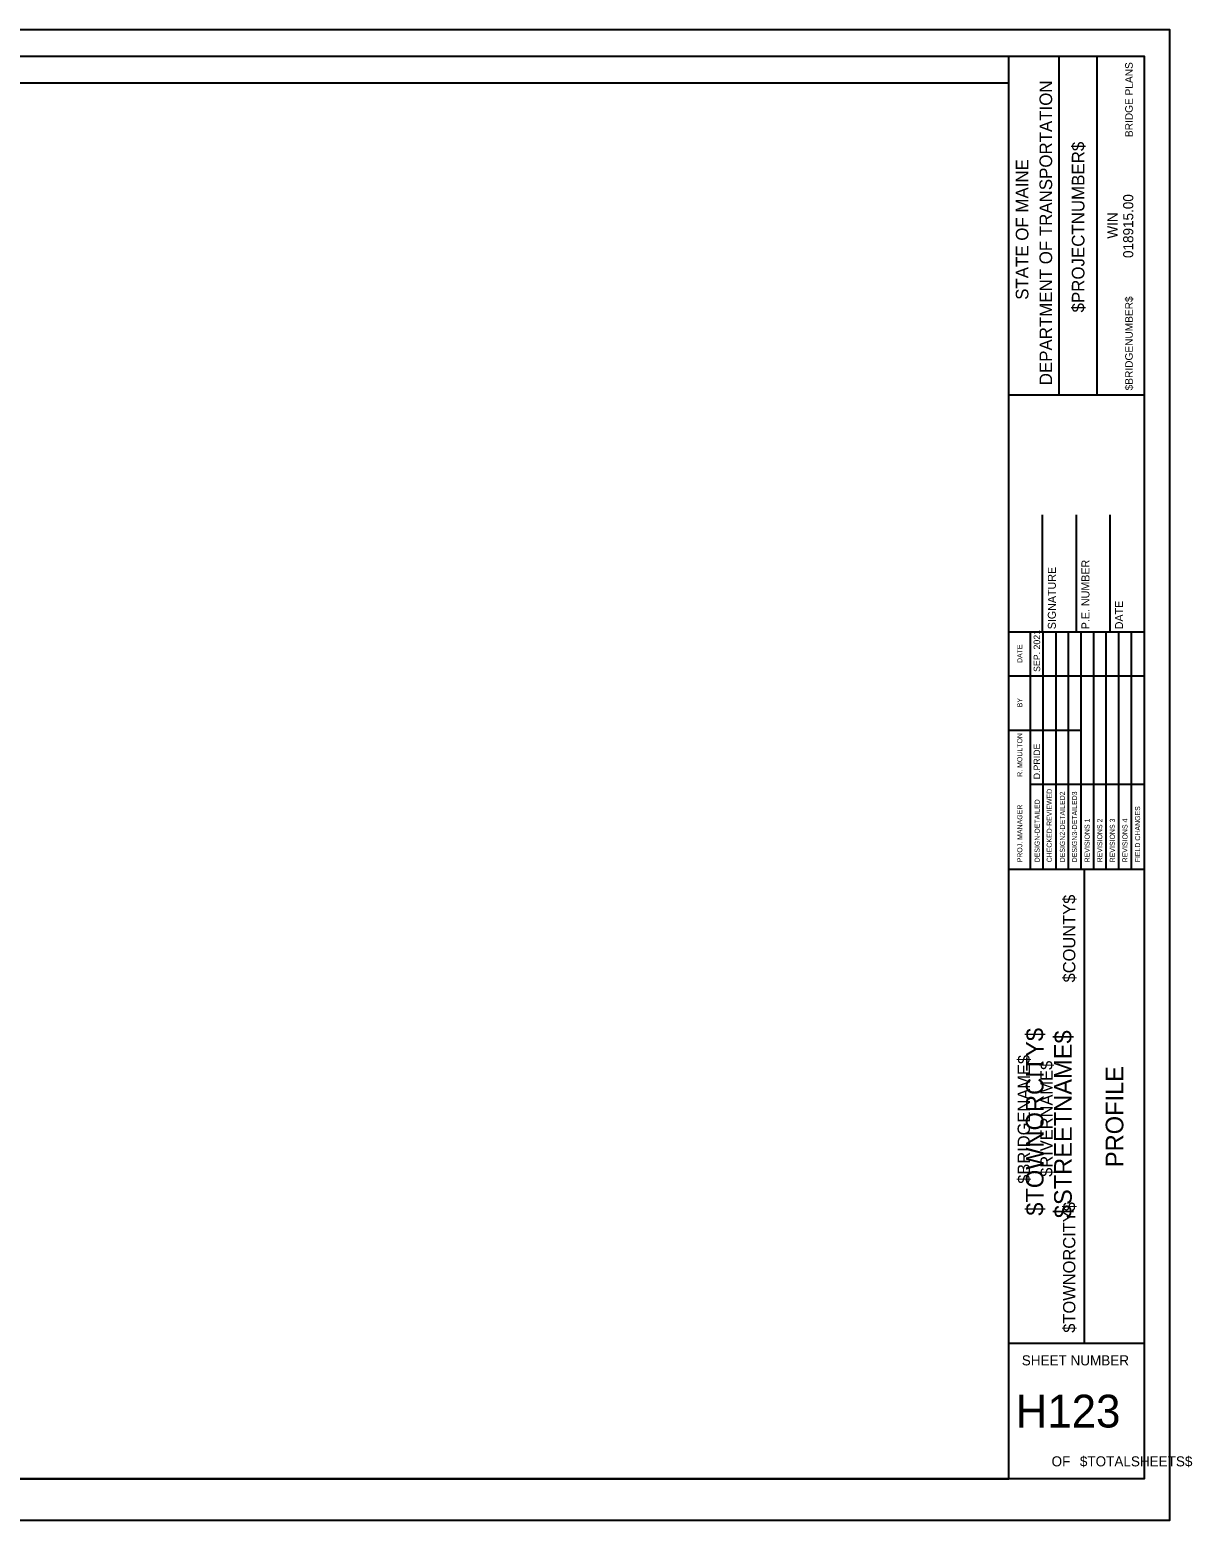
# Model space of a CAD drawing. Extents: x 53120 to 53979, y 9985 to 10535.
# Drawn here: x 53549 to 53979, y 9985 to 10535 of the extents above; entities that cross this region are included whole.
import ezdxf

# ---------------------------------------------------------------- set-up
doc = ezdxf.new("R2010")
doc.units = 0
for name, color, linetype in [('BORDER', 7, 'Continuous'), ('BRIDGE_TITLE', 7, 'Continuous'), ('CLIPS', 7, 'Continuous'), ('HIGHWAY_TITLE', 7, 'Continuous'), ('PLOT BOUNDARY', 7, 'Continuous')]:
    doc.layers.add(name, color=color, linetype=linetype)

msp = doc.modelspace()

# ---------------------------------------------------------------- linework, layer by layer
at = {"layer": 'BORDER'}
for p, q in [((53910.79, 10000), (53910.79, 10525)), ((53929.43, 10399.99), (53929.43, 10524.99)), ((53943.41, 10399.99), (53943.41, 10524.99)), ((53910.79, 10399.97), (53960.79, 10399.97)), ((53923.29, 10312.51), (53923.29, 10355.75)), ((53935.79, 10312.51), (53935.79, 10355.75)), ((53948.29, 10312.51), (53948.29, 10355.75)), ((53910.79, 10312.51), (53960.79, 10312.51)), ((53910.79, 10225.01), (53960.79, 10225.01)), ((53938.74, 10050.01), (53938.74, 10225.01)), ((53910.79, 10050.01), (53960.79, 10050.01))]:
    msp.add_line(p, q, dxfattribs=at)
msp.add_lwpolyline([(53160.79, 10525), (53960.79, 10525), (53960.79, 10000), (53160.79, 10000)], close=True, dxfattribs=at)
for points in [[(53918.86, 10296.26), (53918.86, 10312.51)], [(53923.53, 10225.03), (53923.53, 10312.51)], [(53928.18, 10312.51), (53928.18, 10225.03)], [(53932.84, 10225.03), (53932.84, 10312.51)], [(53937.5, 10225.03), (53937.5, 10312.51)], [(53942.16, 10225.03), (53942.16, 10312.51)], [(53946.82, 10225.03), (53946.82, 10312.51)], [(53951.48, 10225.03), (53951.48, 10312.51)], [(53956.13, 10225.03), (53956.13, 10312.51)], [(53918.87, 10225.03), (53918.87, 10308.98)], [(53910.79, 10296.26), (53960.79, 10296.26)], [(53910.79, 10276.26), (53918.87, 10276.26)], [(53918.86, 10276.26), (53937.5, 10276.26)], [(53918.86, 10256.26), (53960.79, 10256.26)]]:
    msp.add_lwpolyline(points, dxfattribs=at)
at = {"layer": 'CLIPS'}
msp.add_lwpolyline([(53160.79, 10000), (53910.79, 10000), (53910.79, 10515), (53160.79, 10515)], close=True, dxfattribs=at)
at = {"layer": 'PLOT BOUNDARY'}
msp.add_lwpolyline([(53120.32, 9984.7), (53970.32, 9984.7), (53970.32, 10534.7), (53120.32, 10534.7)], close=True, dxfattribs=at)

# ---------------------------------------------------------------- texts
at = {"layer": 'BORDER'}
for s, height, rotation, p in [('DEPARTMENT OF TRANSPORTATION', 4.6588, 90, (53926.82, 10403.53)), ('$PROJECTNUMBER$', 4.6588, 90, (53938.75, 10430.4)), ('STATE OF MAINE', 4.6588, 90, (53918.06, 10435.06)), ('018915.00', 3.726, 90, (53956.77, 10450.49)), ('WIN', 3.726, 90, (53950.97, 10457.65)), ('SIGNATURE', 2.953, 90, (53928.19, 10313.48)), ('P.E. NUMBER', 2.9528, 90, (53940.59, 10313.48)), ('DATE', 2.953, 90, (53952.99, 10313.48)), ('SEP. 2021', 2.423, 90, (53922.4, 10297.74)), ('DATE', 1.857, 90, (53915.81, 10301.04)), ('BY', 1.857, 90, (53915.81, 10284.69)), ('R. MOULTON', 1.864, 90, (53915.81, 10259.03)), ('D.PRIDE', 2.423, 90, (53922.4, 10258.13)), ('CHECKED-REVIEWED', 1.8637, 90, (53926.69, 10227.46)), ('DESIGN2-DETAILED2', 1.8637, 90, (53931.54, 10227.46)), ('DESIGN3-DETAILED3', 1.8637, 90, (53936.01, 10227.46)), ('PROJ. MANAGER', 1.8637, 90, (53915.81, 10227.46)), ('DESIGN-DETAILED', 1.8637, 90, (53922.22, 10227.46)), ('FIELD CHANGES', 1.8637, 90, (53959.3, 10227.46)), ('REVISIONS 1', 1.8637, 90, (53940.67, 10227.46)), ('REVISIONS 2', 1.8637, 90, (53945.33, 10227.46)), ('REVISIONS 3', 1.8637, 90, (53949.98, 10227.46)), ('REVISIONS 4', 1.8637, 90, (53954.64, 10227.46)), ('PROFILE', 6.521, 90, (53953.11, 10115)), ('SHEET NUMBER', 3.7264, 360, (53915.62, 10041.83)), ('H123', 12.097, 360, (53913.36, 10018.91)), ('OF', 3.726, 360, (53926.62, 10004.56)), ('$TOTALSHEETS$', 3.7264, 360, (53937.07, 10004.56))]:
    msp.add_text(s, height=height, rotation=rotation, dxfattribs=at).set_placement(p)
at = {"layer": 'BRIDGE_TITLE'}
for s, height, p in [('BRIDGE PLANS', 2.795, (53956.58, 10495.12)), ('$BRIDGENUMBER$', 2.795, (53956.58, 10401.65)), ('$COUNTY$', 4.536, (53935.39, 10183.17)), ('$BRIDGENAME$', 4.5358, (53918.62, 10108.86)), ('$RIVERNAME$', 4.5358, (53927, 10111.43)), ('$TOWNORCITY$', 4.5358, (53935.39, 10053.88))]:
    msp.add_text(s, height=height, rotation=90, dxfattribs=at).set_placement(p)
at = {"layer": 'HIGHWAY_TITLE'}
for s, p in [('$TOWNORCITY$', (53923.65, 10097.06)), ('$STREETNAME$', (53934.08, 10096.16))]:
    msp.add_text(s, height=6.5214, rotation=90, dxfattribs=at).set_placement(p)

doc.saveas('drawing.dxf')
